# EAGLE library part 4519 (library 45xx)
4-bit AND/OR SELECTOR
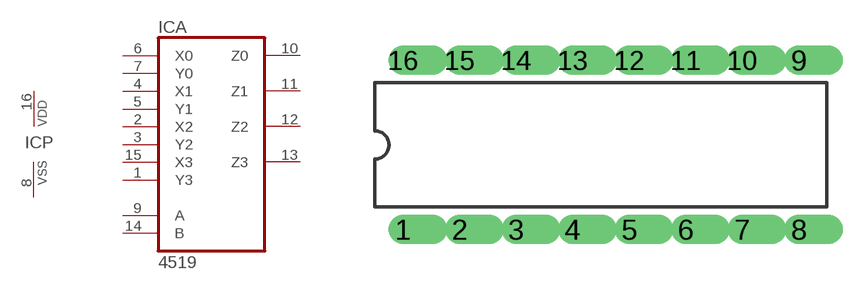
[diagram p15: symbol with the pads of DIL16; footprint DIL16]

Designator prefix IC; gates A=4519 P=PWRN

## 4519N  [DIL16]
1  A:Y3  in
2  A:X2  in
3  A:Y2  in
4  A:X1  in
5  A:Y1  in
6  A:X0  in
7  A:Y0  in
8  P:VSS  pwr
9  A:A  in
10  A:Z0  out
11  A:Z1  out
12  A:Z2  out
13  A:Z3  out
14  A:B  in
15  A:X3  in
16  P:VDD  pwr

## Footprint DIL16 (pad centres in mm)
Dual In Line
drill 0.813 offset: 1 -8.89,-3.81; 2 -6.35,-3.81; 3 -3.81,-3.81; 4 -1.27,-3.81; 5 1.27,-3.81; 6 3.81,-3.81; 7 6.35,-3.81; 8 8.89,-3.81; 9 8.89,3.81; 10 6.35,3.81; 11 3.81,3.81; 12 1.27,3.81; 13 -1.27,3.81; 14 -3.81,3.81; 15 -6.35,3.81; 16 -8.89,3.81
